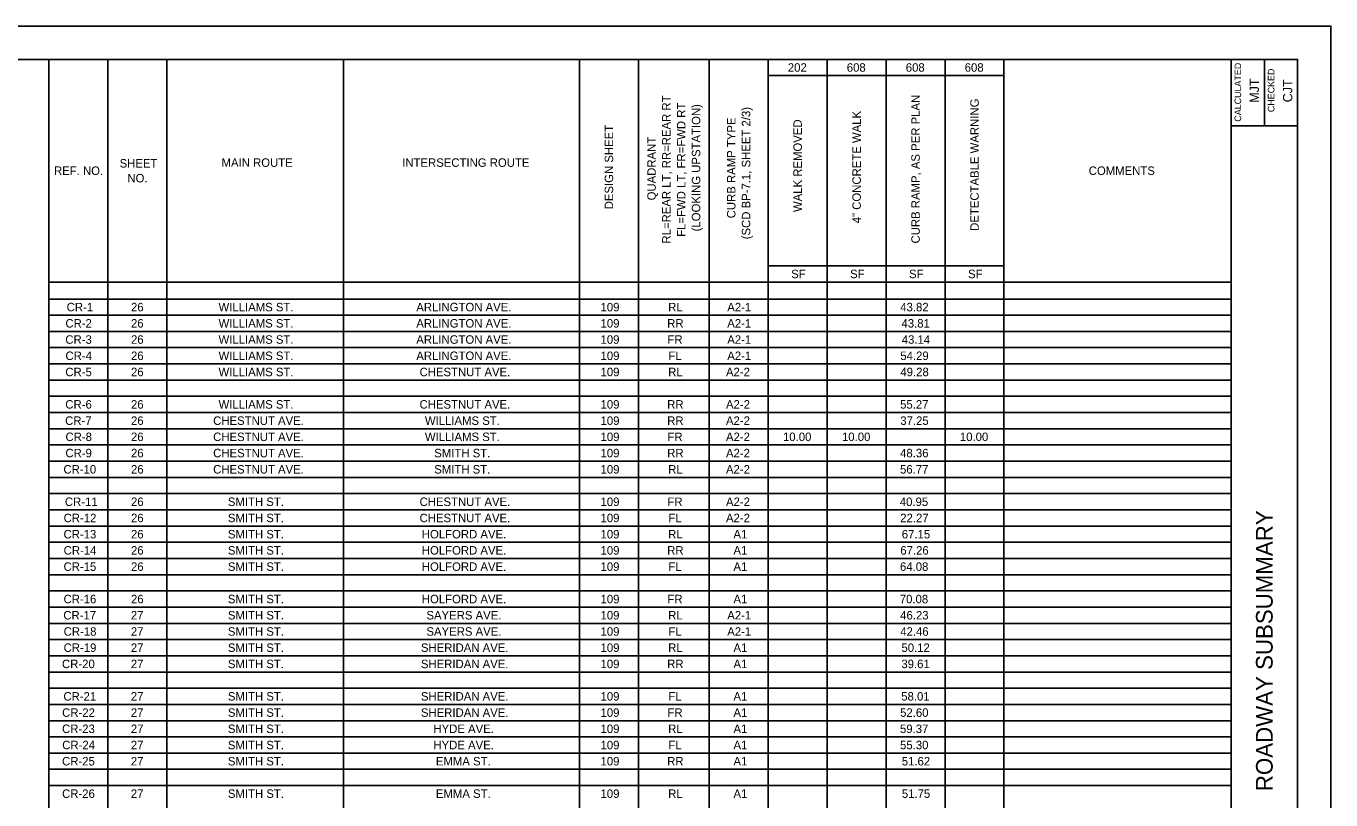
# Model space of a CAD drawing. Extents: x -16 to 102, y -13 to 9.
# Drawn here: x -1.97 to 17.63, y -2.53 to 9.09 of the extents above; entities that cross this region are included whole.
import ezdxf

# ---------------------------------------------------------------- set-up
doc = ezdxf.new("R2010")
doc.units = 0
for name, color, linetype in [('SH_Border', 7, 'Continuous'), ('SH_Cut_Line', 7, 'Continuous'), ('SH_Data', 7, 'Continuous'), ('TX_P_1', 7, 'Continuous')]:
    doc.layers.add(name, color=color, linetype=linetype)

msp = doc.modelspace()

# ---------------------------------------------------------------- linework, layer by layer
at = {"layer": 'SH_Border'}
for p, q in [((16.129, -12.407), (16.129, 8.593)), ((16.629, 8.593), (16.629, 7.593)), ((16.129, 7.593), (17.129, 7.593))]:
    msp.add_line(p, q, dxfattribs=at)
msp.add_lwpolyline([(-14.371, 8.593), (17.129, 8.593), (17.129, -12.407), (-14.371, -12.407)], close=True, dxfattribs=at)
at = {"layer": 'SH_Cut_Line'}
msp.add_lwpolyline([(-16.371, -12.907), (17.629, -12.907), (17.629, 9.093), (-16.371, 9.093)], close=True, dxfattribs=at)
at = {"layer": 'TX_P_1'}
for p, q in [((-1.628, 8.593), (16.129, 8.593)), ((-1.628, 8.593), (-1.628, 7.165)), ((-0.742, 8.593), (-0.742, 7.165)), ((0.144, 8.593), (0.144, 7.165)), ((2.8, 8.593), (2.8, 7.165)), ((6.343, 8.593), (6.343, 7.165)), ((7.228, 8.593), (7.228, 7.165)), ((8.291, 8.593), (8.291, 7.165)), ((9.177, 8.593), (9.177, 7.165)), ((10.062, 8.593), (10.062, 7.165)), ((10.948, 8.593), (10.948, 7.165)), ((11.834, 8.593), (11.834, 7.165)), ((12.719, 8.593), (12.719, 7.165)), ((16.129, 8.593), (16.129, 7.165)), ((9.177, 8.35), (12.719, 8.35)), ((-1.628, 7.165), (-1.628, 6.921)), ((-0.742, 7.165), (-0.742, 6.921)), ((0.144, 7.165), (0.144, 6.921)), ((2.8, 7.165), (2.8, 6.921)), ((6.343, 7.165), (6.343, 6.921)), ((7.228, 7.165), (7.228, 6.921)), ((8.291, 7.165), (8.291, 6.921)), ((9.177, 7.165), (9.177, 6.921)), ((10.062, 7.165), (10.062, 6.921)), ((10.948, 7.165), (10.948, 6.921)), ((11.834, 7.165), (11.834, 6.921)), ((12.719, 7.165), (12.719, 6.921)), ((16.129, 7.165), (16.129, 6.921)), ((-1.628, 6.921), (-1.628, 6.689)), ((-0.742, 6.921), (-0.742, 6.689)), ((0.144, 6.921), (0.144, 6.689)), ((2.8, 6.921), (2.8, 6.689)), ((6.343, 6.921), (6.343, 6.689)), ((7.228, 6.921), (7.228, 6.689)), ((8.291, 6.921), (8.291, 6.689)), ((9.177, 6.921), (9.177, 6.689)), ((10.062, 6.921), (10.062, 6.689)), ((10.948, 6.921), (10.948, 6.689)), ((11.834, 6.921), (11.834, 6.689)), ((12.719, 6.921), (12.719, 6.689)), ((16.129, 6.921), (16.129, 6.689)), ((-1.628, 6.689), (-1.628, 5.737)), ((-0.742, 6.689), (-0.742, 5.737)), ((0.144, 6.689), (0.144, 5.737)), ((2.8, 6.689), (2.8, 5.737)), ((6.343, 6.689), (6.343, 5.737)), ((7.228, 6.689), (7.228, 5.737)), ((8.291, 6.689), (8.291, 5.737)), ((9.177, 6.689), (9.177, 5.737)), ((10.062, 6.689), (10.062, 5.737)), ((10.948, 6.689), (10.948, 5.737)), ((11.834, 6.689), (11.834, 5.737)), ((12.719, 6.689), (12.719, 5.737)), ((16.129, 6.689), (16.129, 5.737)), ((-1.628, 5.737), (-1.628, 4.508)), ((-0.742, 5.737), (-0.742, 4.508)), ((0.144, 5.737), (0.144, 4.508)), ((2.8, 5.737), (2.8, 4.508)), ((6.343, 5.737), (6.343, 4.508)), ((7.228, 5.737), (7.228, 4.508)), ((8.291, 5.737), (8.291, 4.508)), ((9.177, 5.737), (9.177, 4.508)), ((10.062, 5.737), (10.062, 4.508)), ((10.948, 5.737), (10.948, 4.508)), ((11.834, 5.737), (11.834, 4.508)), ((12.719, 5.737), (12.719, 4.508)), ((16.129, 5.737), (16.129, 4.508)), ((9.177, 5.493), (12.719, 5.493)), ((-1.628, 5.25), (16.129, 5.25)), ((-1.628, 4.995), (16.129, 4.995)), ((-1.628, 4.752), (16.129, 4.752)), ((-1.628, 4.508), (16.129, 4.508)), ((-1.628, 4.508), (-1.628, 4.021)), ((-0.742, 4.508), (-0.742, 4.021)), ((0.144, 4.508), (0.144, 4.021)), ((2.8, 4.508), (2.8, 4.021)), ((6.343, 4.508), (6.343, 4.021)), ((7.228, 4.508), (7.228, 4.021)), ((8.291, 4.508), (8.291, 4.021)), ((9.177, 4.508), (9.177, 4.021)), ((10.062, 4.508), (10.062, 4.021)), ((10.948, 4.508), (10.948, 4.021)), ((11.834, 4.508), (11.834, 4.021)), ((12.719, 4.508), (12.719, 4.021)), ((16.129, 4.508), (16.129, 4.021)), ((-1.628, 4.265), (16.129, 4.265)), ((-1.628, 4.021), (16.129, 4.021)), ((-1.628, 4.021), (-1.628, 3.047)), ((-0.742, 4.021), (-0.742, 3.047)), ((0.144, 4.021), (0.144, 3.047)), ((2.8, 4.021), (2.8, 3.047)), ((6.343, 4.021), (6.343, 3.047)), ((7.228, 4.021), (7.228, 3.047)), ((8.291, 4.021), (8.291, 3.047)), ((9.177, 4.021), (9.177, 3.047)), ((10.062, 4.021), (10.062, 3.047)), ((10.948, 4.021), (10.948, 3.047)), ((11.834, 4.021), (11.834, 3.047)), ((12.719, 4.021), (12.719, 3.047)), ((16.129, 4.021), (16.129, 3.047)), ((-1.628, 3.778), (16.129, 3.778)), ((-1.628, 3.534), (16.129, 3.534)), ((-1.628, 3.291), (16.129, 3.291)), ((-1.628, 3.047), (16.129, 3.047)), ((-1.628, 3.047), (-1.628, 1.829)), ((-0.742, 3.047), (-0.742, 1.829)), ((0.144, 3.047), (0.144, 1.829)), ((2.8, 3.047), (2.8, 1.829)), ((6.343, 3.047), (6.343, 1.829)), ((7.228, 3.047), (7.228, 1.829)), ((8.291, 3.047), (8.291, 1.829)), ((9.177, 3.047), (9.177, 1.829)), ((10.062, 3.047), (10.062, 1.829)), ((10.948, 3.047), (10.948, 1.829)), ((11.834, 3.047), (11.834, 1.829)), ((12.719, 3.047), (12.719, 1.829)), ((16.129, 3.047), (16.129, 1.829)), ((-1.628, 2.803), (16.129, 2.803)), ((-1.628, 2.56), (16.129, 2.56)), ((-1.628, 2.316), (16.129, 2.316)), ((-1.628, 2.073), (16.129, 2.073)), ((-1.628, 1.829), (16.129, 1.829)), ((-1.628, 1.829), (-1.628, 0.612)), ((-0.742, 1.829), (-0.742, 0.612)), ((0.144, 1.829), (0.144, 0.612)), ((2.8, 1.829), (2.8, 0.612)), ((6.343, 1.829), (6.343, 0.612)), ((7.228, 1.829), (7.228, 0.612)), ((8.291, 1.829), (8.291, 0.612)), ((9.177, 1.829), (9.177, 0.612)), ((10.062, 1.829), (10.062, 0.612)), ((10.948, 1.829), (10.948, 0.612)), ((11.834, 1.829), (11.834, 0.612)), ((12.719, 1.829), (12.719, 0.612)), ((16.129, 1.829), (16.129, 0.612)), ((-1.628, 1.586), (16.129, 1.586)), ((-1.628, 1.342), (16.129, 1.342)), ((-1.628, 1.099), (16.129, 1.099)), ((-1.628, 0.855), (16.129, 0.855)), ((-1.628, 0.612), (16.129, 0.612)), ((-1.628, 0.612), (-1.628, -0.606)), ((-0.742, 0.612), (-0.742, -0.606)), ((0.144, 0.612), (0.144, -0.606)), ((2.8, 0.612), (2.8, -0.606)), ((6.343, 0.612), (6.343, -0.606)), ((7.228, 0.612), (7.228, -0.606)), ((8.291, 0.612), (8.291, -0.606)), ((9.177, 0.612), (9.177, -0.606)), ((10.062, 0.612), (10.062, -0.606)), ((10.948, 0.612), (10.948, -0.606)), ((11.834, 0.612), (11.834, -0.606)), ((12.719, 0.612), (12.719, -0.606)), ((16.129, 0.612), (16.129, -0.606)), ((-1.628, 0.368), (16.129, 0.368)), ((-1.628, 0.125), (16.129, 0.125)), ((-1.628, -0.119), (16.129, -0.119)), ((-1.628, -0.363), (16.129, -0.363)), ((-1.628, -0.606), (16.129, -0.606)), ((-1.628, -0.606), (-1.628, -1.58)), ((-0.742, -0.606), (-0.742, -1.58)), ((0.144, -0.606), (0.144, -1.58)), ((2.8, -0.606), (2.8, -1.58)), ((6.343, -0.606), (6.343, -1.58)), ((7.228, -0.606), (7.228, -1.58)), ((8.291, -0.606), (8.291, -1.58)), ((9.177, -0.606), (9.177, -1.58)), ((10.062, -0.606), (10.062, -1.58)), ((10.948, -0.606), (10.948, -1.58)), ((11.834, -0.606), (11.834, -1.58)), ((12.719, -0.606), (12.719, -1.58)), ((16.129, -0.606), (16.129, -1.58)), ((-1.628, -0.85), (16.129, -0.85)), ((-1.628, -1.093), (16.129, -1.093)), ((-1.628, -1.337), (16.129, -1.337)), ((-1.628, -1.58), (16.129, -1.58)), ((-1.628, -1.58), (-1.628, -2.067)), ((-0.742, -1.58), (-0.742, -2.067)), ((0.144, -1.58), (0.144, -2.067)), ((2.8, -1.58), (2.8, -2.067)), ((6.343, -1.58), (6.343, -2.067)), ((7.228, -1.58), (7.228, -2.067)), ((8.291, -1.58), (8.291, -2.067)), ((9.177, -1.58), (9.177, -2.067)), ((10.062, -1.58), (10.062, -2.067)), ((10.948, -1.58), (10.948, -2.067)), ((11.834, -1.58), (11.834, -2.067)), ((12.719, -1.58), (12.719, -2.067)), ((16.129, -1.58), (16.129, -2.067)), ((-1.628, -1.824), (16.129, -1.824)), ((-1.628, -2.067), (16.129, -2.067)), ((-1.628, -2.067), (-1.628, -2.798)), ((-0.742, -2.067), (-0.742, -2.798)), ((0.144, -2.067), (0.144, -2.798)), ((2.8, -2.067), (2.8, -2.798)), ((6.343, -2.067), (6.343, -2.798)), ((7.228, -2.067), (7.228, -2.798)), ((8.291, -2.067), (8.291, -2.798)), ((9.177, -2.067), (9.177, -2.798)), ((10.062, -2.067), (10.062, -2.798)), ((10.948, -2.067), (10.948, -2.798)), ((11.834, -2.067), (11.834, -2.798)), ((12.719, -2.067), (12.719, -2.798)), ((16.129, -2.067), (16.129, -2.798)), ((-1.628, -2.311), (16.129, -2.311))]:
    msp.add_line(p, q, dxfattribs=at)

# ---------------------------------------------------------------- texts
at = {"layer": 'SH_Data'}
for s, height, p in [('CALCULATED', 0.1, (16.281, 7.658)), ('CHECKED', 0.1, (16.781, 7.801)), ('MJT', 0.14, (16.549, 7.942)), ('CJT', 0.14, (17.049, 7.949)), ('ROADWAY SUBSUMMARY', 0.25, (16.754, -2.395))]:
    msp.add_text(s, height=height, rotation=90, dxfattribs=at).set_placement(p)
at = {"layer": 'TX_P_1'}
for s, height, p in [('202', 0.1273, (9.473, 8.408)), ('608', 0.1273, (10.358, 8.408)), ('608', 0.1273, (11.244, 8.408)), ('608', 0.1273, (12.129, 8.408)), ('SHEET', 0.1273, (-0.563, 6.969)), ('MAIN ROUTE', 0.1273, (0.968, 6.98)), ('INTERSECTING ROUTE', 0.12731, (3.681, 6.98)), ('REF. NO.', 0.1273, (-1.548, 6.858)), ('NO.', 0.1273, (-0.446, 6.746)), ('COMMENTS', 0.1273, (13.992, 6.858)), ('SF', 0.1273, (9.523, 5.308)), ('SF', 0.1273, (10.408, 5.308)), ('SF', 0.1273, (11.294, 5.308)), ('SF', 0.1273, (12.179, 5.308)), ('CR-1', 0.1273, (-1.358, 4.81)), ('26', 0.1273, (-0.392, 4.81)), ('WILLIAMS ST.', 0.12731, (0.923, 4.81)), ('ARLINGTON AVE.', 0.12731, (3.893, 4.81)), ('109', 0.1273, (6.66, 4.81)), ('RL', 0.1273, (7.676, 4.81)), ('A2-1', 0.1273, (8.563, 4.81)), ('43.82', 0.1273, (11.161, 4.81)), ('CR-2', 0.1273, (-1.377, 4.566)), ('26', 0.1273, (-0.392, 4.566)), ('WILLIAMS ST.', 0.12731, (0.923, 4.566)), ('ARLINGTON AVE.', 0.12731, (3.893, 4.566)), ('109', 0.1273, (6.66, 4.566)), ('RR', 0.1273, (7.661, 4.566)), ('A2-1', 0.1273, (8.563, 4.566)), ('43.81', 0.1273, (11.18, 4.566)), ('CR-3', 0.1273, (-1.378, 4.323)), ('26', 0.1273, (-0.392, 4.323)), ('WILLIAMS ST.', 0.12731, (0.923, 4.323)), ('ARLINGTON AVE.', 0.12731, (3.893, 4.323)), ('109', 0.1273, (6.66, 4.323)), ('FR', 0.1273, (7.665, 4.323)), ('A2-1', 0.1273, (8.563, 4.323)), ('43.14', 0.1273, (11.184, 4.323)), ('CR-4', 0.1273, (-1.376, 4.079)), ('26', 0.1273, (-0.392, 4.079)), ('WILLIAMS ST.', 0.12731, (0.923, 4.079)), ('ARLINGTON AVE.', 0.12731, (3.893, 4.079)), ('109', 0.1273, (6.66, 4.079)), ('FL', 0.1273, (7.68, 4.079)), ('A2-1', 0.1273, (8.563, 4.079)), ('54.29', 0.1273, (11.162, 4.079)), ('CR-5', 0.1273, (-1.378, 3.836)), ('26', 0.1273, (-0.392, 3.836)), ('WILLIAMS ST.', 0.12731, (0.923, 3.836)), ('CHESTNUT AVE.', 0.12731, (3.942, 3.836)), ('109', 0.1273, (6.66, 3.836)), ('RL', 0.1273, (7.676, 3.836)), ('A2-2', 0.1273, (8.544, 3.836)), ('49.28', 0.1273, (11.163, 3.836)), ('CR-6', 0.1273, (-1.378, 3.349)), ('26', 0.1273, (-0.392, 3.349)), ('WILLIAMS ST.', 0.12731, (0.923, 3.349)), ('CHESTNUT AVE.', 0.12731, (3.942, 3.349)), ('109', 0.1273, (6.66, 3.349)), ('RR', 0.1273, (7.661, 3.349)), ('A2-2', 0.1273, (8.544, 3.349)), ('55.27', 0.1273, (11.159, 3.349)), ('CR-7', 0.1273, (-1.381, 3.105)), ('26', 0.1273, (-0.392, 3.105)), ('CHESTNUT AVE.', 0.12731, (0.842, 3.105)), ('WILLIAMS ST.', 0.12731, (4.022, 3.105)), ('109', 0.1273, (6.66, 3.105)), ('RR', 0.1273, (7.661, 3.105)), ('A2-2', 0.1273, (8.544, 3.105)), ('37.25', 0.1273, (11.162, 3.105)), ('CR-8', 0.1273, (-1.376, 2.862)), ('26', 0.1273, (-0.392, 2.862)), ('CHESTNUT AVE.', 0.12731, (0.842, 2.862)), ('WILLIAMS ST.', 0.12731, (4.022, 2.862)), ('109', 0.1273, (6.66, 2.862)), ('FR', 0.1273, (7.665, 2.862)), ('A2-2', 0.1273, (8.544, 2.862)), ('10.00', 0.1273, (9.4, 2.862)), ('10.00', 0.1273, (10.286, 2.862)), ('10.00', 0.1273, (12.057, 2.862)), ('CR-9', 0.1273, (-1.377, 2.618)), ('26', 0.1273, (-0.392, 2.618)), ('CHESTNUT AVE.', 0.12731, (0.842, 2.618)), ('SMITH ST.', 0.1273, (4.162, 2.618)), ('109', 0.1273, (6.66, 2.618)), ('RR', 0.1273, (7.661, 2.618)), ('A2-2', 0.1273, (8.544, 2.618)), ('48.36', 0.1273, (11.159, 2.618)), ('CR-10', 0.1273, (-1.407, 2.374)), ('26', 0.1273, (-0.392, 2.374)), ('CHESTNUT AVE.', 0.12731, (0.842, 2.374)), ('SMITH ST.', 0.1273, (4.162, 2.374)), ('109', 0.1273, (6.66, 2.374)), ('RL', 0.1273, (7.676, 2.374)), ('A2-2', 0.1273, (8.544, 2.374)), ('56.77', 0.1273, (11.158, 2.374)), ('CR-11', 0.1273, (-1.385, 1.887)), ('26', 0.1273, (-0.392, 1.887)), ('SMITH ST.', 0.1273, (1.063, 1.887)), ('CHESTNUT AVE.', 0.12731, (3.942, 1.887)), ('109', 0.1273, (6.66, 1.887)), ('FR', 0.1273, (7.665, 1.887)), ('A2-2', 0.1273, (8.544, 1.887)), ('40.95', 0.1273, (11.154, 1.887)), ('CR-12', 0.1273, (-1.404, 1.644)), ('26', 0.1273, (-0.392, 1.644)), ('SMITH ST.', 0.1273, (1.063, 1.644)), ('CHESTNUT AVE.', 0.12731, (3.942, 1.644)), ('109', 0.1273, (6.66, 1.644)), ('FL', 0.1273, (7.68, 1.644)), ('A2-2', 0.1273, (8.544, 1.644)), ('22.27', 0.1273, (11.161, 1.644)), ('CR-13', 0.1273, (-1.405, 1.4)), ('26', 0.1273, (-0.392, 1.4)), ('SMITH ST.', 0.1273, (1.063, 1.4)), ('HOLFORD AVE.', 0.12731, (3.976, 1.4)), ('109', 0.1273, (6.66, 1.4)), ('RL', 0.1273, (7.676, 1.4)), ('A1', 0.1273, (8.656, 1.4)), ('67.15', 0.1273, (11.184, 1.4)), ('CR-14', 0.1273, (-1.403, 1.157)), ('26', 0.1273, (-0.392, 1.157)), ('SMITH ST.', 0.1273, (1.063, 1.157)), ('HOLFORD AVE.', 0.12731, (3.976, 1.157)), ('109', 0.1273, (6.66, 1.157)), ('RR', 0.1273, (7.661, 1.157)), ('A1', 0.1273, (8.656, 1.157)), ('67.26', 0.1273, (11.162, 1.157)), ('CR-15', 0.1273, (-1.405, 0.913)), ('26', 0.1273, (-0.392, 0.913)), ('SMITH ST.', 0.1273, (1.063, 0.913)), ('HOLFORD AVE.', 0.12731, (3.976, 0.913)), ('109', 0.1273, (6.66, 0.913)), ('FL', 0.1273, (7.68, 0.913)), ('A1', 0.1273, (8.656, 0.913)), ('64.08', 0.1273, (11.157, 0.913)), ('CR-16', 0.1273, (-1.405, 0.426)), ('26', 0.1273, (-0.392, 0.426)), ('SMITH ST.', 0.1273, (1.063, 0.426)), ('HOLFORD AVE.', 0.12731, (3.976, 0.426)), ('109', 0.1273, (6.66, 0.426)), ('FR', 0.1273, (7.665, 0.426)), ('A1', 0.1273, (8.656, 0.426)), ('70.08', 0.1273, (11.154, 0.426)), ('CR-17', 0.1273, (-1.408, 0.183)), ('27', 0.1273, (-0.394, 0.183)), ('SMITH ST.', 0.1273, (1.063, 0.183)), ('SAYERS AVE.', 0.12731, (4.045, 0.183)), ('109', 0.1273, (6.66, 0.183)), ('RL', 0.1273, (7.676, 0.183)), ('A2-1', 0.1273, (8.563, 0.183)), ('46.23', 0.1273, (11.16, 0.183)), ('CR-18', 0.1273, (-1.403, -0.061)), ('27', 0.1273, (-0.394, -0.061)), ('SMITH ST.', 0.1273, (1.063, -0.061)), ('SAYERS AVE.', 0.12731, (4.045, -0.061)), ('109', 0.1273, (6.66, -0.061)), ('FL', 0.1273, (7.68, -0.061)), ('A2-1', 0.1273, (8.563, -0.061)), ('42.46', 0.1273, (11.161, -0.061)), ('CR-19', 0.1273, (-1.404, -0.304)), ('27', 0.1273, (-0.394, -0.304)), ('SMITH ST.', 0.1273, (1.063, -0.304)), ('SHERIDAN AVE.', 0.12731, (3.962, -0.304)), ('109', 0.1273, (6.66, -0.304)), ('RL', 0.1273, (7.676, -0.304)), ('A1', 0.1273, (8.656, -0.304)), ('50.12', 0.1273, (11.179, -0.304)), ('CR-20', 0.1273, (-1.428, -0.548)), ('27', 0.1273, (-0.394, -0.548)), ('SMITH ST.', 0.1273, (1.063, -0.548)), ('SHERIDAN AVE.', 0.12731, (3.962, -0.548)), ('109', 0.1273, (6.66, -0.548)), ('RR', 0.1273, (7.661, -0.548)), ('A1', 0.1273, (8.656, -0.548)), ('39.61', 0.1273, (11.178, -0.548)), ('CR-21', 0.1273, (-1.407, -1.035)), ('27', 0.1273, (-0.394, -1.035)), ('SMITH ST.', 0.1273, (1.063, -1.035)), ('SHERIDAN AVE.', 0.12731, (3.962, -1.035)), ('109', 0.1273, (6.66, -1.035)), ('FL', 0.1273, (7.68, -1.035)), ('A1', 0.1273, (8.656, -1.035)), ('58.01', 0.1273, (11.176, -1.035)), ('CR-22', 0.1273, (-1.426, -1.279)), ('27', 0.1273, (-0.394, -1.279)), ('SMITH ST.', 0.1273, (1.063, -1.279)), ('SHERIDAN AVE.', 0.12731, (3.962, -1.279)), ('109', 0.1273, (6.66, -1.279)), ('FR', 0.1273, (7.665, -1.279)), ('A1', 0.1273, (8.656, -1.279)), ('52.60', 0.1273, (11.159, -1.279)), ('CR-23', 0.1273, (-1.427, -1.522)), ('27', 0.1273, (-0.394, -1.522)), ('SMITH ST.', 0.1273, (1.063, -1.522)), ('HYDE AVE.', 0.1273, (4.15, -1.522)), ('109', 0.1273, (6.66, -1.522)), ('RL', 0.1273, (7.676, -1.522)), ('A1', 0.1273, (8.656, -1.522)), ('59.37', 0.1273, (11.157, -1.522)), ('CR-24', 0.1273, (-1.425, -1.766)), ('27', 0.1273, (-0.394, -1.766)), ('SMITH ST.', 0.1273, (1.063, -1.766)), ('HYDE AVE.', 0.1273, (4.15, -1.766)), ('109', 0.1273, (6.66, -1.766)), ('FL', 0.1273, (7.68, -1.766)), ('A1', 0.1273, (8.656, -1.766)), ('55.30', 0.1273, (11.158, -1.766)), ('CR-25', 0.1273, (-1.427, -2.009)), ('27', 0.1273, (-0.394, -2.009)), ('SMITH ST.', 0.1273, (1.063, -2.009)), ('EMMA ST.', 0.1273, (4.187, -2.009)), ('109', 0.1273, (6.66, -2.009)), ('RR', 0.1273, (7.661, -2.009)), ('A1', 0.1273, (8.656, -2.009)), ('51.62', 0.1273, (11.184, -2.009)), ('CR-26', 0.1273, (-1.427, -2.496)), ('27', 0.1273, (-0.394, -2.496)), ('SMITH ST.', 0.1273, (1.063, -2.496)), ('EMMA ST.', 0.1273, (4.187, -2.496)), ('109', 0.1273, (6.66, -2.496)), ('RL', 0.1273, (7.676, -2.496)), ('A1', 0.1273, (8.656, -2.496)), ('51.75', 0.1273, (11.185, -2.496))]:
    msp.add_text(s, height=height, dxfattribs=at).set_placement(p)
for s, height, p in [('RL=REAR LT, RR=REAR RT', 0.12731, (7.712, 5.828)), ('CURB RAMP, AS PER PLAN', 0.12731, (11.454, 5.829)), ('FL=FWD LT, FR=FWD RT', 0.12731, (7.935, 5.929)), ('(LOOKING UPSTATION)', 0.12731, (8.158, 6.011)), ('(SCD BP-7.1, SHEET 2/3)', 0.12731, (8.909, 5.892)), ('DETECTABLE WARNING', 0.12731, (12.34, 6.018)), ('CURB RAMP TYPE', 0.12731, (8.686, 6.207)), ('WALK REMOVED', 0.12731, (9.683, 6.301)), ('4" CONCRETE WALK', 0.12731, (10.569, 6.132)), ('DESIGN SHEET', 0.12731, (6.849, 6.342)), ('QUADRANT', 0.1273, (7.489, 6.476))]:
    msp.add_text(s, height=height, rotation=90, dxfattribs=at).set_placement(p)

doc.saveas('drawing.dxf')
